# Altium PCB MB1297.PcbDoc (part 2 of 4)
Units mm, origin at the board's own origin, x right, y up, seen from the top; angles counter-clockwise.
Board outline 90.1 x 62.11 mm, 4 copper layers (Top Layer, GND, POWER+GND, Bottom Layer), stack 0.778 mm thick; 235 components, 175 nets, 1727 pads, 1 vias.
Unrouted connection lines stored in the file: 1.
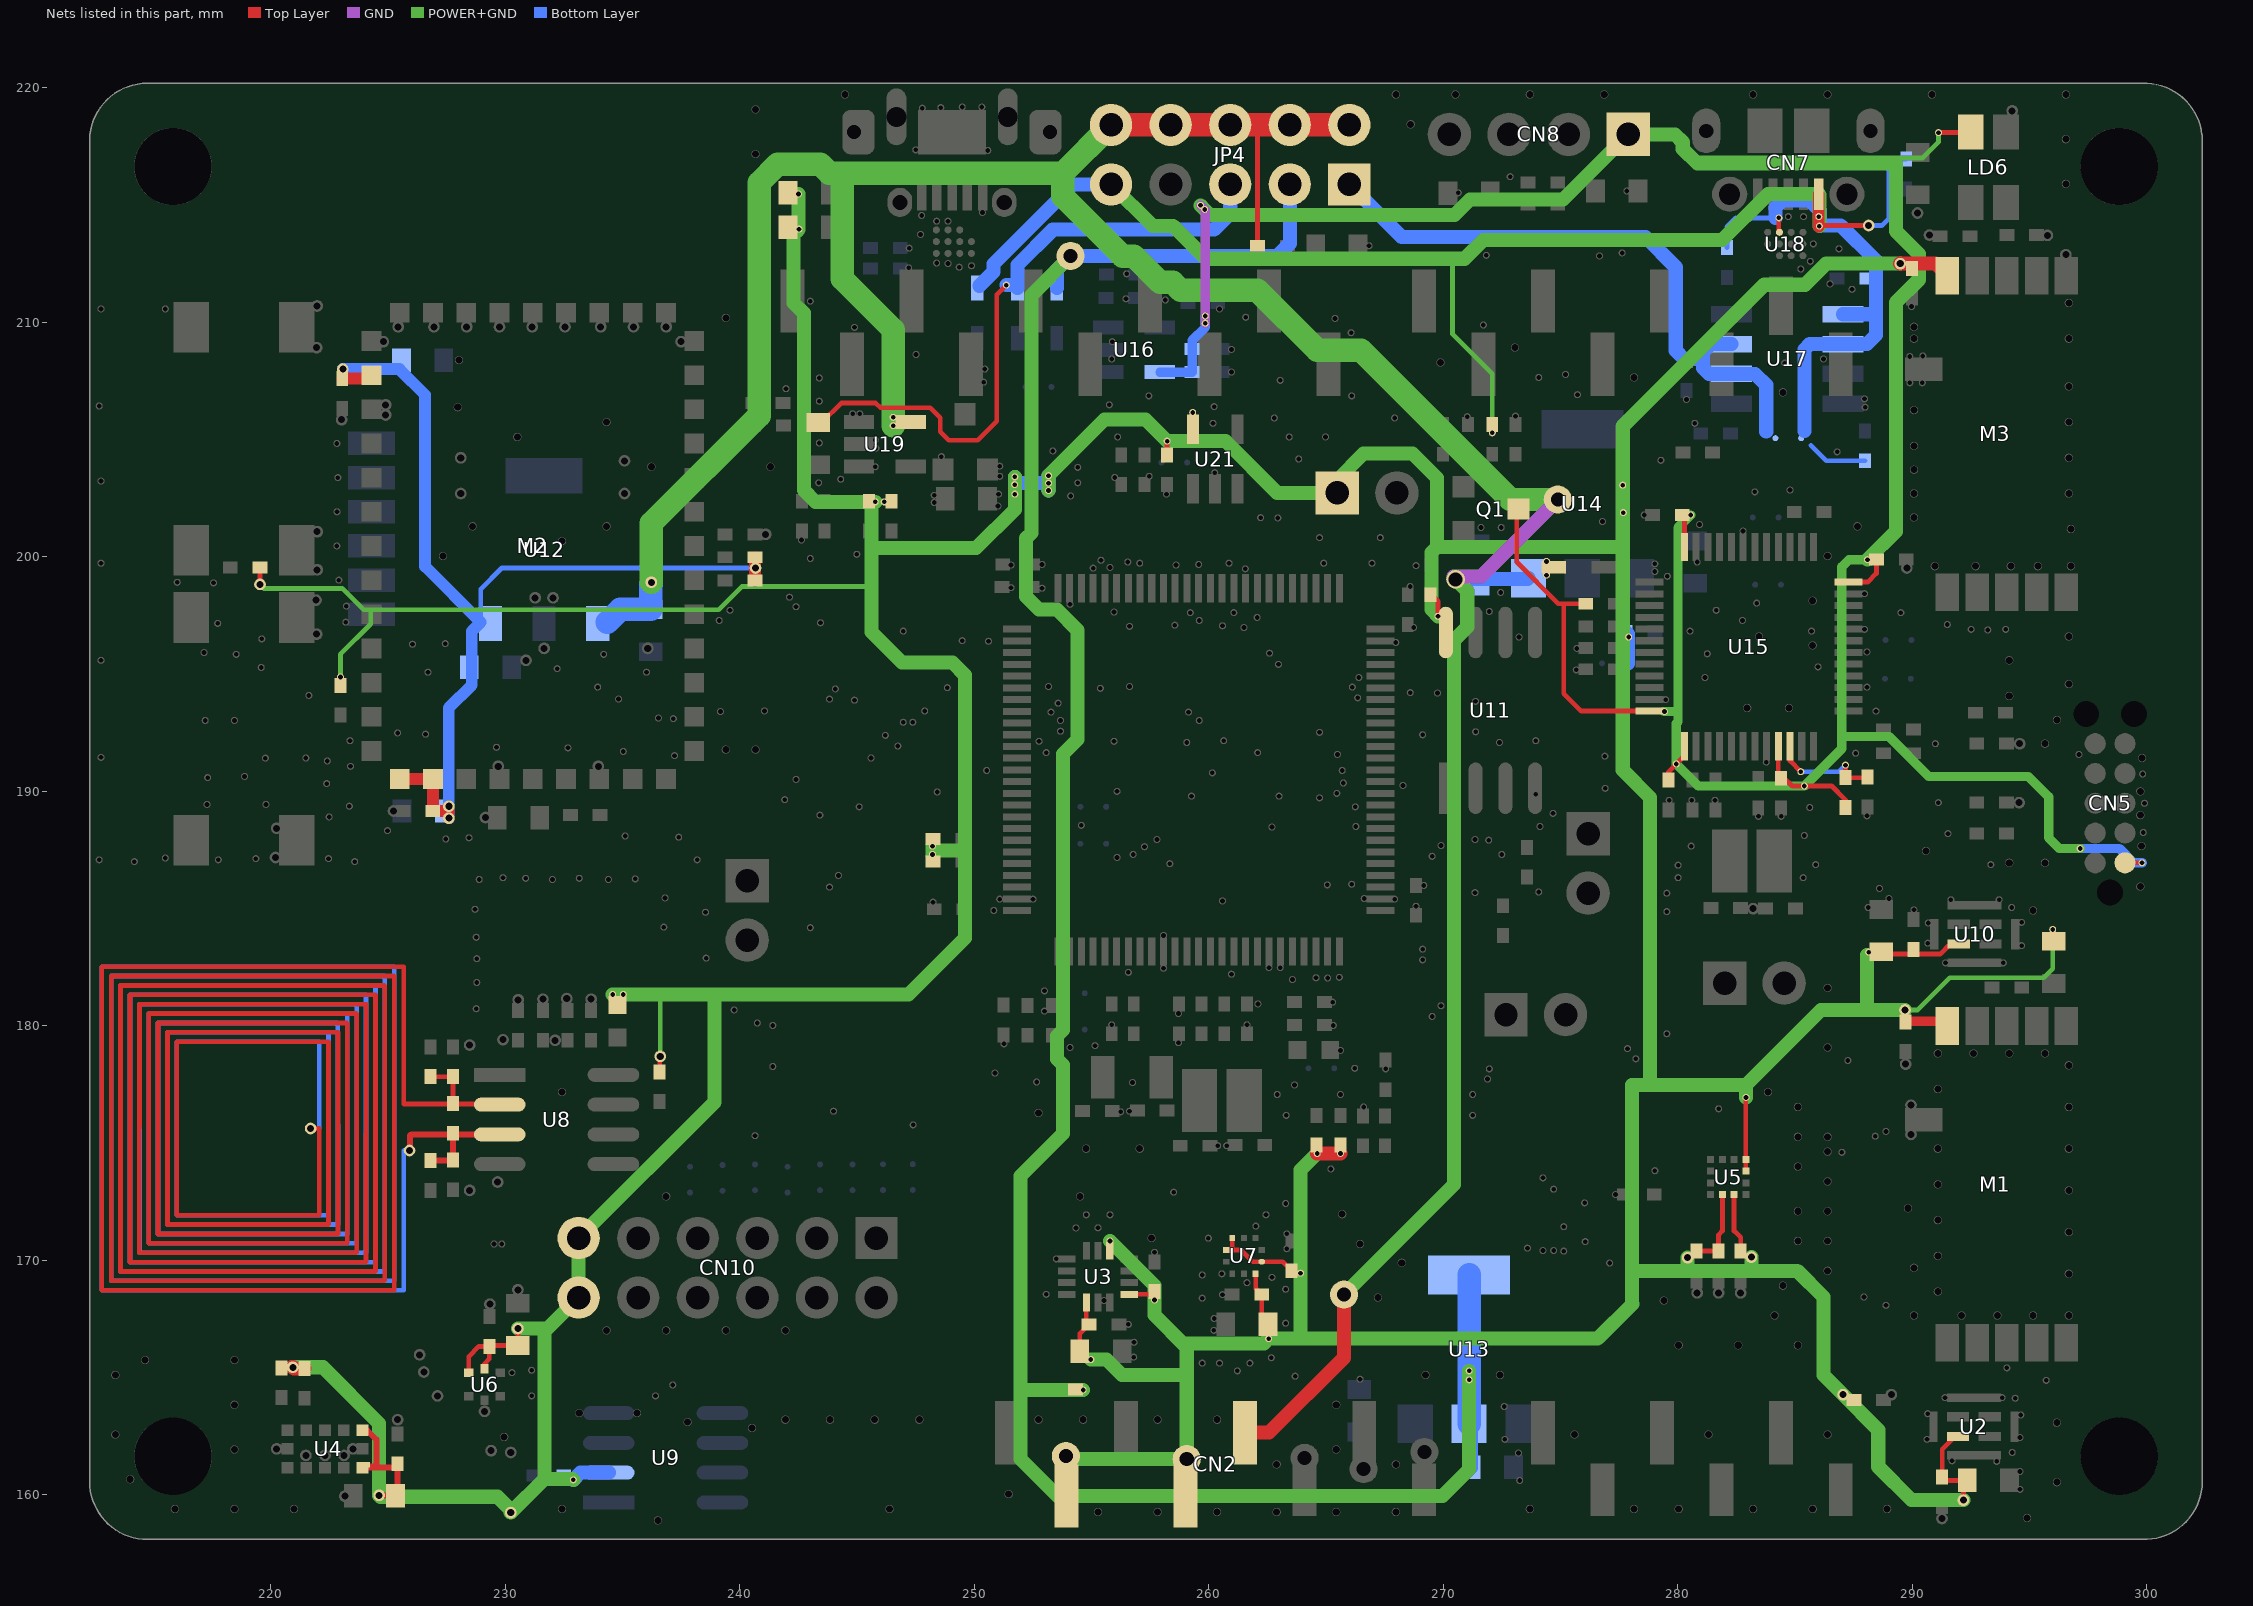
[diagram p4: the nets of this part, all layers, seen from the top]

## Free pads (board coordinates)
  round 0.3 hole 0.2 mask+0.05: 0(212.75,210.566) 0(232.893,160.63) 0(240.643,175.307) 0(247.747,214.554) 0(299.822,190.729) 1(215.494,210.566) 1(222.811,204.828) 1(247.384,175.768) 1(248.387,214.308) 1(299.847,188.239) 2(212.674,187.071) 2(222.853,203.371) 2(237.134,164.677) 2(243.992,176.352) 2(248.387,212.522) 2(299.796,186.944) 3(215.494,187.147) 3(222.818,201.914) 3(236.398,164.211) 3(279.933,191.16) 4(214.173,186.995) 4(222.809,200.457) 4(249.352,212.344) 4(285.394,190.221) 5(212.75,191.44) 5(222.894,199) 5(249.873,212.407) 5(279.476,193.904) 6(212.75,195.58) 6(223.215,197.891) 6(248.869,214.308) 6(287.96,198.425) 7(212.75,199.72) 7(223.19,197.206) 7(248.873,212.5) 7(287.96,196.901) 8(212.75,203.225) 8(247.701,213.741) 8(262.585,195.885) 8(283.769,191.237) 9(212.674,206.426) 9(255.397,199.847) 9(262.966,195.406) 9(288.087,199.873) 10(217.551,198.882) 10(255.778,199.542) 10(280.822,199.771) 11(216.002,198.907) 11(263.271,172.415) 11(278.562,201.778) 11(284.709,214.503) 12(217.729,197.155) 12(262.433,171.933) 12(280.543,201.778) 12(285.359,214.503) 13(217.297,190.576) 13(255.778,171.933) 13(282.778,201.092) 13(285.241,212.268) 14(218.872,190.627) 14(254.77,171.933) 14(284.782,202.842) 14(285.648,212.598) 15(217.195,193.015) 15(231.115,164.211) 15(275.692,196.088) 15(285.776,213.34) 16(218.44,193.015) 16(231.115,165.303) 16(275.666,195.174) 16(284.306,214.448) 17(217.145,195.91) 17(255.27,171.378) 17(286.009,214.503) 18(218.516,195.834) 18(254.33,171.374) 18(283.282,202.764) 18(286.034,214.097) 19(222.377,190.322) 19(251.358,211.582) 19(262.914,177.063) 19(289.966,210.668) 20(223.342,189.357) 20(245.11,206.096) 20(263.296,176.174) 20(286.791,204.47) 21(217.754,187.071) 21(248.285,202.616) 21(264.617,174.549) 21(292.506,196.901) 22(219.354,187.122) 22(248.285,202.311) 22(265.608,174.549) 22(293.218,196.875) 23(217.272,189.433) 23(253.06,168.541) 23(263.041,207.52) 23(293.98,196.901) 24(219.786,189.433) 24(262.056,197.409) 24(263.423,205.105) 25(222.479,188.9) 25(259.588,197.282) 25(263.83,204.165) 25(288.417,175.285) 26(222.453,187.122) 26(259.207,197.612) 27(223.571,186.995) 27(247.51,208.623) 27(253.263,193.37) 27(288.874,175.489) 28(228.879,186.233) 28(247.193,212.319) 28(253.67,193.015) 28(276.901,190.121) 29(228.752,180.721) 29(247.218,213.157) 29(259.588,193.015) 29(280.01,186.842) 30(228.778,181.839) 30(259.131,193.37) 30(263.563,181.966) 31(228.778,182.855) 31(262.077,191.643) 31(262.687,188.468) 31(293.345,186.868) 32(228.752,183.769) 32(253.06,191.643) 32(256.769,187.3) 32(285.877,186.868) 33(228.702,184.963) 33(234.569,181.331) 33(249.479,196.418) 33(274.117,188.493) 34(229.895,186.309) 34(235.026,181.331) 34(279.527,185.649) 35(230.861,186.284) 35(253.67,192.557) 35(261.214,165.278) 35(285.623,189.306) 36(232.004,186.233) 36(260.579,197.053) 36(262.09,180.924) 36(280.01,186.309) 37(233.147,186.284) 37(260.553,169.418) 37(260.629,192.151) 37(285.344,186.309) 38(234.391,186.233) 38(253.344,204.509) 38(261.62,169.037) 38(285.394,188.112) 39(235.534,186.258) 39(259.977,170.934) 39(280.568,187.655) 40(236.753,184.201) 40(261.493,196.977) 40(274.676,189.052) 41(236.804,185.445) 41(262.001,171.45) 41(279.425,193.396) 42(224.968,188.316) 42(263.906,169.443) 42(279.527,179.654) 43(227.457,187.96) 43(260.579,168.529) 43(263.652,177.47) 43(276.885,191.491) 43(277.851,179.019) 44(228.448,188.011) 44(260.223,167.513) 44(266.217,178.181) 44(278.206,178.587) 45(235.102,188.087) 45(260.21,167.005) 45(266.598,176.53) 45(281.635,197.714) 45(299.898,189.484) 46(237.388,188.036) 46(262.547,166.649) 46(267.538,178.156) 46(279.527,184.861) 46(297.104,191.567) 47(238.176,187.071) 47(252.984,181.483) 47(254.635,164.465) 47(271.348,185.674) 48(238.531,184.836) 48(254.965,165.76) 48(256.565,182.27) 49(238.557,182.88) 49(274.066,185.699) 50(239.751,180.67) 50(254.076,179.07) 50(256.807,166.497) 50(264.719,200.812) 50(283.362,198.018) 51(229.616,191.872) 51(255.143,179.146) 51(256.794,165.862) 51(264.897,199.72) 52(232.664,191.846) 52(256.565,167.259) 52(258.699,180.518) 52(271.932,187.909) 53(235.026,191.694) 53(256.083,187.173) 53(257.683,168.3) 53(272.491,187.3) 53(277.647,203.048) 54(237.211,191.516) 54(254.559,188.544) 54(257.683,170.332) 54(271.348,187.935) 54(277.673,201.879) 55(236.525,193.116) 55(255.524,168.275) 55(256.083,189.992) 55(272.44,198.476) 56(230.276,165.202) 56(237.16,193.091) 56(255.778,170.815) 57(229.845,170.688) 57(239.166,193.396) 57(243.002,184.175) 57(253.492,170.053) 57(271.704,209.88) 58(229.514,170.688) 58(240.741,180.111) 58(241.046,193.421) 58(266.09,206.858) 58(269.748,194.183) 59(236.017,195.072) 59(241.402,180.01) 59(266.827,213.258) 59(269.113,192.405) 59(289.89,208.534) 60(232.207,195.224) 60(241.402,178.257) 60(268.586,194.202) 60(290.449,208.559) 61(234.188,195.834) 61(266.624,185.42) 61(272.39,192.075) 61(289.89,207.416) 62(226.695,195.072) 62(267.919,185.395) 62(271.374,192.532) 62(290.424,207.416) 63(227.432,196.291) 63(258.14,210.947) 63(268.834,185.09) 63(271.372,193.829) 63(280.365,206.705) 64(226.035,196.266) 64(256.489,212.065) 64(269.164,185.979) 64(273.939,192.151) 64(280.721,205.689) 65(219.761,191.409) 65(256.464,210.998) 65(260.147,190.779) 65(273.939,189.865) 65(287.96,206.731) 66(221.488,191.414) 66(260.96,208.839) 66(263.042,182.474) 66(271.958,197.663) 66(287.985,206.375) 67(221.615,194.081) 67(260.96,207.874) 67(269.773,197.46) 67(284.556,208.255) 68(219.583,195.275) 68(268.732,196.977) 68(275.209,207.772) 69(219.608,196.494) 69(262.56,182.474) 69(267.97,196.342) 69(271.831,212.852) 69(286.207,208.432) 70(222.402,191.287) 70(264.566,182.042) 70(272.618,162.357) 70(276.657,212.827) 70(288.061,195.936) 71(223.393,191.059) 71(265.063,182.03) 71(272.593,163.754) 71(279.552,199.164) 71(288.061,194.437) 72(223.368,192.151) 72(265.563,182.062) 72(273.202,161.773) 72(291.118,218.084) 72(291.516,188.189) 73(225.4,192.481) 73(257.251,187.63) 73(273.253,160.604) 73(297.155,187.554) 74(226.593,192.43) 74(272.466,201.244) 74(286.868,213.131) 74(291.109,189.509) 75(255.372,194.386) 75(265.379,210.16) 75(271.602,201.244) 75(275.133,171.425) 75(290.982,192.024) 76(253.162,194.462) 76(253.162,202.819) 76(266.954,199.72) 76(275.133,170.383) 76(288.112,185.039) 77(253.162,203.454) 77(272.847,216.205) 77(274.245,170.409) 77(289.001,185.42) 78(253.162,203.136) 78(274.701,170.409) 78(290.068,184.937) 79(251.723,203.403) 79(276.047,170.79) 79(288.138,183.134) 80(251.714,203.073) 80(276.022,172.441) 80(290.678,184.379) 81(251.723,202.667) 81(266.065,209.55) 81(274.245,173.506) 81(290.659,183.515) 82(247.777,219.126) 82(274.701,173.025) 82(291.643,185.369) 83(222.961,194.869) 83(248.564,219.151) 83(257.785,187.936) 83(293.7,185.369) 84(250.317,219.177) 84(258.33,186.906) 84(294.659,184.404) 85(250.571,217.322) 85(265.049,186.004) 85(277.622,212.954) 85(294.659,183.413) 86(247.498,217.348) 86(266.09,186.03) 86(279.274,204.11) 86(291.414,182.677) 87(249.479,219.177) 87(269.519,187.223) 87(293.878,182.677) 88(250.342,214.681) 88(269.9,187.681) 88(295.986,184.099) 89(250.444,208.001) 89(269.519,180.391) 89(291.389,164.135) 90(250.393,207.442) 90(269.9,180.848) 90(293.827,164.135) 91(269.113,183.261) 91(279.019,173.812) 91(294.625,163.398) 92(269.113,182.804) 92(281.737,176.454) 92(294.589,162.433) 93(251.257,179.222) 93(253.568,193.751) 94(252.984,180.619) 94(294.259,161.798) 95(250.596,196.393) 95(256.743,177.571) 95(290.652,163.449) 96(290.627,162.357) 97(252.652,177.597) 97(254.076,197.968) 97(291.694,161.442) 98(293.599,161.417) 99(255.063,199.513) 99(294.589,160.985) 100(294.589,160.223) 101(242.113,198.272) 101(266.446,164.922) 102(242.392,197.866) 102(287.579,191.618) 103(242.392,190.5) 103(288.449,193.414) 104(241.91,189.636) 104(287.147,191.11) 105(263.271,168.758) 105(285.242,190.83) 106(243.408,188.976) 106(263.271,167.31) 106(288.061,188.951) 107(243.434,197.18) 107(262.687,169.266) 107(283.439,188.925) 108(245.085,189.332) 108(259.715,169.367) 108(284.404,188.925) 109(248.412,189.967) 109(259.715,168.377) 109(281.584,189.611) 110(244.881,209.779) 110(259.715,165.608) 110(280.594,189.611) 111(243.002,210.896) 111(260.452,165.608) 111(279.629,189.611) 112(245.77,202.336) 112(258.064,183.845) 112(261.747,165.608) 113(246.151,202.336) 113(258.064,182.448) 113(262.661,165.837) 114(242.621,200.711) 114(263.677,165.049) 115(243.002,199.923) 115(260.96,182.194) 115(265.278,181) 116(246.532,205.943) 116(260.579,185.318) 116(265.303,180.01) 117(246.532,205.588) 117(262.992,189.789) 117(265.608,178.943) 118(245.77,204.978) 118(259.258,189.789) 119(245.796,204.622) 119(259.055,192.075) 119(261.62,180.035) 120(258.597,199.644) 120(258.699,179.273) 121(245.77,203.835) 121(255.854,180.035) 121(259.563,199.669) 122(251.079,203.429) 122(260.375,174.879) 122(262.941,201.651) 123(251.079,203.86) 123(254.406,203.81) 123(260.756,174.879) 124(251.028,202.667) 124(254.406,203.149) 124(256.235,176.327) 125(251.003,202.159) 125(255.753,206.477) 125(256.616,176.352) 126(244.805,206.096) 126(260.172,205.689) 126(270.637,215.519) 127(251.562,199.644) 127(260.223,206.4) 127(277.825,215.595) 128(242.494,215.468) 128(251.562,198.679) 128(261.569,210.21) 129(242.519,213.97) 129(243.383,207.62) 129(252.882,199.669) 130(243.383,206.629) 130(247.371,192.938) 130(252.882,198.656) 131(243.383,204.851) 131(246.202,192.38) 131(262.204,201.663) 132(243.357,203.149) 132(246.736,191.922) 132(261.553,199.482) 133(244.983,200.101) 133(245.593,191.414) 133(266.243,189.332) 134(244.881,193.878) 134(266.268,188.493) 135(250.825,184.912) 135(265.735,190.348) 136(251.079,185.395) 136(265.684,190.881) 137(252.501,185.395) 137(266.395,194.843) 138(266.116,194.437) 139(266.344,193.98) 140(248.209,187.3) 140(265.455,189.906) 141(248.209,187.655) 141(265.481,191.567) 142(248.234,185.268) 143(247.879,193.421) 143(268.58,198.73) 144(241.96,207.162) 144(248.844,194.412) 145(244.2,186.406) 145(244.297,203.302) 146(243.818,185.906) 146(248.59,204.267) 147(244.069,194.361) 148(243.818,193.925) 149(239.116,197.282) 149(277.343,172.796) 150(239.573,197.714) 150(282.905,176.936) 151(271.247,176.174) 152(246.964,192.938) 152(271.247,177.063) 153(233.934,194.437) 153(265.608,177.063) 154(234.823,193.929) 155(246.964,196.825) 155(258.547,197.079) 156(250.52,190.881) 156(258.496,172.898) 157(273.583,170.51) 159(277.089,169.875) 160(291.49,197.104) 161(288.874,168.072) 162(295.707,164.871) 163(294.03,165.405) 164(287.934,168.427) 165(294.386,164.109) 166(294.234,185.039) 167(286.995,174.6) 168(288.595,185.852) 169(287.249,178.511) 171(257.438,206.858) 172(257.454,203.429) 173(258.191,202.667) 174(259.309,206.146) 175(260.248,203.581) 177(258.216,204.927) 179(257.048,199.72) 180(256.54,199.771) 181(256.108,205.105)
  round 3.3 hole 3.3 unplated mask+0.05: 0(215.819,161.64) 0(215.819,216.64) 0(298.819,161.64) 0(298.819,216.64)
  round 0.5 hole 0.3 mask+0.05: 0(225.908,174.676) 0(229.387,161.874) 0(288.138,214.122) 1(221.691,175.614) 1(230.226,161.798) 1(290.22,214.655) 2(229.337,168.123) 2(230.53,168.732) 3(229.146,188.874) 4(227.584,189.357) 4(230.226,159.233) 5(223.152,159.931) 5(227.584,188.849) 6(224.612,159.969) 6(231.648,196.088) 7(223.491,161.95) 7(231.267,198.247) 8(223.114,161.671) 8(232.029,198.247) 9(222.301,161.671) 9(228.092,204.216) 10(221.488,161.671) 10(228.092,202.692) 11(220.243,161.95) 11(235.077,204.089) 12(225.4,163.195) 12(235.077,202.692) 13(220.929,165.43) 14(227.101,164.211) 15(229.108,163.551) 15(236.22,198.907) 16(224.79,209.169) 16(230.53,167.081) 17(225.425,209.804) 17(226.517,165.227) 18(226.339,165.964) 18(226.949,209.804) 19(228.346,209.804) 20(229.743,209.804) 21(231.14,209.804) 22(232.537,209.804) 23(234.061,209.804) 24(228.473,179.172) 24(235.458,209.804) 25(228.473,172.974) 25(236.855,209.804) 26(229.667,173.33) 26(237.49,209.169) 27(230.543,181.102) 27(240.665,199.517) 28(231.597,181.127) 28(241.097,200.952) 29(232.613,181.153) 30(233.655,181.127) 31(232.118,179.375) 32(229.895,179.4) 33(236.601,178.689) 37(292.176,159.766) 39(291.262,158.979) 44(287.045,164.262) 45(289.103,164.262) 50(294.577,192.024) 51(294.551,189.509) 54(289.687,180.67) 56(289.941,176.606) 57(289.941,175.362) 58(289.712,178.359) 68(283.134,170.129) 69(280.416,170.104) 70(280.822,168.605) 71(281.737,168.605) 72(282.677,168.605) 81(289.763,199.517) 82(283.21,184.988) 83(223.063,208.001) 84(223.012,205.842) 85(224.892,206.477) 86(224.892,206.045) 87(219.532,198.819) 88(230.873,195.58) 89(236.068,196.088) 91(225.222,189.154) 92(229.692,191.059) 93(233.959,191.059) 94(220.243,188.417) 95(220.193,187.173) 96(221.92,198.145) 97(221.945,196.698) 98(221.971,201.066) 99(221.971,199.441) 100(221.971,210.693) 101(221.945,208.915) 107(294.259,219.011) 108(296.545,212.877) 109(289.484,212.496) 110(290.728,213.716) 111(295.758,213.703)
  round 1.2 hole 0.6 mask+0.05: 48(253.897,161.645) 48(254.102,212.827) 48(259.054,161.518) 48(264.083,161.568) 48(265.76,168.529) 48(266.597,161.086) 48(269.189,161.823) 48(274.879,202.438)
  round 0.8 hole 0.6 mask+0.05: 48(270.521,199.034)
  round 0.3 hole 0.2 mask-0.01: 182(271.098,165.278) 183(271.098,164.897) 184(256.616,197.028) 186(264.719,189.713) 187(264.719,192.507) 191(255.956,197.637) 192(255.956,192.126) 193(256.616,194.462) 194(252.755,192.126) 195(271.958,178.156) 196(265.201,173.888) 197(250.875,177.978) 198(261.063,197.613) 199(271.882,177.724) 202(260.858,199.72) 203(262.788,205.918) 204(267.919,205.918) 205(274.396,199.212) 206(274.396,199.796) 207(272.085,205.283) 208(259.639,214.986) 209(259.817,214.808) 210(259.842,210.261) 211(259.842,209.956) 212(254.102,202.59) 213(264.973,205.105) 215(276.784,201.498) 216(282.753,197.282) 217(280.924,201.371) 218(279.019,199.695) 219(279.019,199.365) 221(277.901,196.571) 222(280.518,196.825) 223(275.717,206.908) 224(274.066,207.645) 225(271.018,205.969) 226(273.075,205.994) 228(273.228,196.571) 229(268.276,190.245) 230(268.834,199.619) 231(260.452,210.566) 232(255.88,209.169) 233(255.854,208.432) 234(263.322,171.12) 235(263.322,170.485) 236(255.981,203.378) 237(286.487,211.633) 238(287.426,211.404) 239(281.153,194.843) 241(285.979,195.301) 244(267.31,200.812) 245(289.509,197.612) 246(285.699,196.825) 247(281.254,195.859)
  round 0.35 hole 0.3 mask-0.01: 249(296.672,207.264) 250(296.672,209.296) 251(296.672,210.82) 252(296.672,205.74) 253(296.672,204.216) 254(296.672,202.692) 255(296.759,201.179) 256(296.759,199.593) 257(295.351,199.593) 258(294.198,199.593) 259(292.699,199.593) 260(290.957,199.593) 261(290.068,201.676) 262(290.068,202.692) 263(290.068,203.708) 264(290.068,204.724) 265(290.068,206.248) 266(290.068,209.296) 267(290.068,209.804) 268(296.672,196.596) 269(296.672,194.564) 270(294.132,195.58) 271(294.132,194.056) 272(296.164,193.04) 273(295.656,192.024) 274(295.656,186.944) 275(294.132,186.944) 276(290.576,187.452) 277(295.148,184.912) 278(299.72,185.928) 279(299.72,188.976) 280(299.72,189.992) 281(299.796,191.414) 282(299.771,187.655) 283(296.672,178.308) 284(296.672,176.53) 285(296.672,174.752) 286(296.672,172.974) 287(296.672,171.196) 288(296.672,167.64) 289(296.672,169.418) 290(291.084,178.816) 291(291.084,177.292) 292(291.084,174.752) 293(291.084,173.228) 294(291.084,171.704) 295(291.084,170.18) 296(291.084,168.656) 297(292.1,167.64) 298(293.624,167.64) 299(295.148,167.64) 300(292.608,178.816) 301(294.132,178.816) 302(295.656,178.816) 303(289.814,172.212) 304(290.068,169.672) 305(290.068,167.64) 306(286.385,169.545) 307(286.385,170.815) 308(286.385,172.085) 309(286.385,173.355) 310(286.385,174.625) 311(283.845,177.165) 312(285.115,176.53) 313(286.385,175.26) 314(285.115,175.26) 315(285.115,173.99) 316(285.115,172.085) 317(285.115,170.815) 318(284.48,168.91) 319(284.124,167.64) 320(285.115,166.37) 321(286.385,179.07) 322(286.385,181.61) 327(240.665,219.075) 328(244.475,219.71) 329(240.665,217.17) 330(296.545,219.71) 331(290.83,219.71) 332(296.545,217.805) 333(296.545,215.9) 334(267.97,219.71) 335(268.605,218.44) 336(270.51,219.71) 337(273.685,219.71) 338(276.86,219.71) 339(283.21,219.71) 340(286.385,219.71) 341(273.05,208.915) 342(269.875,208.28) 343(278.13,207.645) 344(284.48,207.01) 345(287.655,201.295) 346(286.385,200.025) 347(285.75,198.12) 348(285.75,196.215) 349(281.305,162.56) 350(283.21,159.385) 351(285.75,159.385) 352(280.035,159.385) 353(278.13,159.385) 354(273.685,159.385) 355(267.97,159.258) 356(265.43,159.258) 357(262.89,159.258) 358(260.35,159.258) 359(257.81,159.258) 360(255.27,159.258) 361(275.59,162.56) 362(265.43,161.925) 363(262.89,161.29) 364(267.97,161.29) 365(269.24,165.1) 366(272.415,165.1) 367(280.035,166.37) 368(282.575,166.37) 369(279.4,168.275) 370(286.385,162.56) 371(288.925,159.385) 372(257.81,163.195) 373(260.35,163.195) 374(254.635,163.195) 375(252.73,163.195) 376(265.43,163.83) 377(251.46,160.02) 378(247.65,163.195) 379(246.38,159.385) 380(236.499,158.902) 381(232.41,159.385) 382(229.946,162.458) 383(220.98,159.385) 384(218.44,159.385) 385(215.9,159.385) 386(213.995,160.655) 387(213.36,162.56) 388(213.36,165.1) 389(214.63,165.735) 390(218.44,165.735) 391(218.44,163.83) 392(218.44,161.925) 393(233.147,163.474) 394(235.61,163.474) 395(237.769,163.093) 396(240.513,162.839) 397(241.935,163.195) 398(243.84,163.195) 399(245.745,163.195) 400(234.315,167.005) 401(236.855,167.005) 402(239.395,167.005) 403(241.935,167.005) 404(232.41,177.165) 405(236.855,172.72) 406(227.965,206.375) 407(230.505,205.105) 408(234.315,205.74) 409(241.3,203.835) 410(236.22,203.835) 411(227.33,200.025) 412(228.6,201.295) 413(232.41,200.66) 414(234.315,201.295) 415(240.665,191.77) 416(239.395,191.77) 417(228.016,208.382) 418(239.395,210.185) 420(252.73,176.276) 421(257.556,170.942) 422(257.048,174.752) 423(254.762,174.752) 424(254.508,172.72) 425(265.684,171.958) 426(266.446,170.688) 427(268.224,169.885) 428(267.208,168.402) 429(296.164,163.068) 430(296.164,160.528) 431(294.894,159.004) 432(282.956,193.548) 433(284.734,193.548) 434(283.464,196.596)

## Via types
v1: diameter 0.4, hole 0.2, Top Layer to Bottom Layer, tented both sides, 1 vias

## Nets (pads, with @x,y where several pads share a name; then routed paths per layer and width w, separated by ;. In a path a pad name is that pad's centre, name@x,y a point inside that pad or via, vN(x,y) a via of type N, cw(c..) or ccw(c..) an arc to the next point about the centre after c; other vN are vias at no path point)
3V3: C16.1 C17.2 C18.1 C19.1 C20.1 C21.1 C22.1 C24.1 C25.1 C26.1 C27.1 C28.1 C29.1 C30.1 C31.1 C33.1 C42.1 C43.1 C45.1 C46.1 C48.1 C73.1 C74.1 CN2.2 CN2.4 CN10.6 CN10.12 JP5.1 L2.2 LD4.A LD8.A LD9.A M1.5 M3.5 pad.0@232.893,160.63 pad.4@230.226,159.233 pad.6@224.612,159.969 pad.13@220.929,165.43 pad.16@230.53,167.081 pad.21@264.617,174.549 pad.22@265.608,174.549 pad.33@234.569,181.331 pad.33@236.601,178.689 pad.34@235.026,181.331 pad.37@292.176,159.766 pad.42@263.906,169.443 pad.44@287.045,164.262 pad.46@262.547,166.649 pad.48@253.897,161.645 pad.48@254.965,165.76 pad.48@259.054,161.518 pad.53@257.683,168.3 pad.53@277.647,203.048 pad.54@277.673,201.879 pad.54@289.687,180.67 pad.56@255.778,170.815 pad.67@269.773,197.46 pad.68@283.134,170.129 pad.69@280.416,170.104 pad.76@253.162,202.819 pad.77@253.162,203.454 pad.78@253.162,203.136 pad.79@251.723,203.403 pad.79@288.138,183.134 pad.80@251.714,203.073 pad.81@251.723,202.667 pad.83@222.961,194.869 pad.87@219.532,198.819 pad.88@295.986,184.099 pad.109@289.484,212.496 pad.112@245.77,202.336 pad.113@246.151,202.336 pad.128@242.494,215.468 pad.129@242.519,213.97 pad.140@248.209,187.3 pad.141@248.209,187.655 pad.150@282.905,176.936 pad.174 pad.177 pad.221 R4.1 R8.1 R9.1 R10.1 R11.1 R14.1 R15.1 R23.2 R26.2 R58.1 R62.1 R67.1 SB4.2 U2.1 U3.5 U3.8 U3.12 U4.1 U4.11 U5.5 U5.6 U5.9 U5.10 U6.1 U6.6 U7.1 U7.5 U7.6 U7.10 U9.2 U10.1 U11.8 U21.5 | length 377.1
  Top Layer w0.204: pad.87@219.532,198.819 R23.2@219.532,199.542 ; U6.1@228.433,165.194 228.433,165.886 228.867,166.319 C28.1@229.311,166.319 ; U6.6@229.108,165.369 229.108,165.583 229.311,165.786 C28.1@229.311,166.319 ; pad.16@230.53,167.081 C27.1@230.53,166.357 229.349,166.357 C28.1@229.311,166.319 ; R4.1@236.576,178.029 pad.33@236.576,178.664 ; C18.1@254.495,166.116 254.495,166.865 C19.1@254.889,167.259 254.77,167.378 U3.5@254.77,168.191 ; U3.8@256.6,168.541 257.568,168.541 C20.1@257.683,168.656 ; C73.1@258.216,204.343 pad.177@258.216,204.927 ; U7.6@260.73,170.43 260.981,170.43 ; U7.5@260.993,170.943 260.993,170.442 261.001,170.434 261.366,170.434 261.87,169.93 U7.1@262.256,169.93 263.14,169.93 C31.1@263.525,169.545 ; U7.10@261.993,169.417 261.993,168.791 C29.1@262.255,168.529 262.255,167.526 C30.1@262.522,167.259 ; C48.1@269.469,198.399 269.773,198.095 pad.67@269.773,197.46 ; U11.8@270.104,195.871 270.104,197.409 U11.8@270.154,197.46 ; C24.1@280.797,170.383 C25.1@281.737,170.383 281.737,171.086 281.897,171.247 U5.5@281.897,172.795 ; U5.6@282.397,172.795 282.397,171.247 282.677,170.967 C26.1@282.677,170.383 ; U5.9@282.897,173.795 U5.10@282.897,174.295 282.897,176.928 pad.150@282.905,176.936 ; C46.1@288.671,183.147 288.765,183.052 291.193,183.052 291.622,183.481 U10.1@291.984,183.481 ; C43.1@289.712,180.162 C43.1@289.738,180.188 ; M1.5@291.186,180.188 291.389,179.984 M1.5@291.49,179.984 ; U2.1@291.95,162.477 291.812,162.477 291.271,161.937 291.271,160.766 C17.2@291.262,160.757 291.414,160.604 292.189,160.604 292.176,160.592 pad.37@292.176,159.766
  Top Layer w0.254: U4.11@223.901,162.75 224.092,162.75 224.501,162.341 224.501,161.198 223.949,161.198 U4.1@223.901,161.15 225.235,161.15 C22.1@225.4,161.315 225.4,160.033 C21.1@225.311,159.944 ; pad.6@224.612,159.969 C21.1@225.285,159.969
  Top Layer w0.4: C43.1@289.738,180.188 M1.5@291.186,180.188
  Top Layer w0.6: pad.13@220.929,165.43 220.98,165.379 R14.1@221.437,165.379 ; pad.21@264.617,174.549 pad.22@265.608,174.549 ; pad.109@289.484,212.496 290.982,212.496 M3.5@291.49,211.988
  POWER+GND w0.204: pad.87@219.532,198.819 219.705,198.646 223.041,198.646 223.948,197.739 224.257,197.739 ; pad.83@222.961,194.869 222.961,195.834 224.257,197.129 224.257,197.739 ; 236.576,181.305 236.601,181.28 pad.33@236.601,178.689 ; 245.61,198.755 245.585,198.73 240.088,198.73 239.098,197.739 224.257,197.739 ; 245.72,200.363 pad.112@245.72,202.286 ; 259.232,204.927 259.309,205.003 pad.174@259.309,206.146 ; pad.54@289.687,180.67 290.22,180.67 291.592,182.042 295.605,182.042 295.986,182.423 pad.88@295.986,184.099
  POWER+GND w0.6: pad.13@220.929,165.43 222.221,165.43 224.612,163.039 pad.6@224.612,159.969 224.671,159.91 229.663,159.91 230.226,159.347 pad.4@230.226,159.233 231.667,160.674 ; pad.16@230.53,167.081 231.8,167.081 ; pad.0@232.893,160.63 232.849,160.674 231.667,160.674 ; pad.33@234.569,181.331 pad.34@235.026,181.331 238.912,181.331 ; pad.128@242.494,215.468 242.494,213.944 242.291,213.741 242.291,210.827 242.722,210.395 242.722,202.844 243.23,202.336 pad.112@245.77,202.336 245.72,202.286 245.61,202.176 245.61,198.755 245.61,196.782 246.913,195.478 249.072,195.478 249.606,194.945 249.606,187.477 ; 245.72,200.363 250.071,200.363 251.723,202.015 pad.81@251.723,202.667 pad.79@251.723,203.403 ; pad.140@248.209,187.3 pad.141@248.209,187.655 248.387,187.477 249.606,187.477 ; pad.76@253.162,202.819 pad.78@253.162,203.136 pad.77@253.162,203.454 255.549,205.842 257.302,205.842 pad.177@258.216,204.927 259.232,204.927 260.706,204.927 262.915,202.717 JP5.1@265.477,202.717 265.477,203.272 266.598,204.394 268.681,204.394 269.723,203.352 269.723,200.41 ; pad.48@253.897,161.645 254.024,161.518 pad.48@259.054,161.518 259.054,165.1 ; pad.48@254.965,165.76 255.626,165.76 256.286,165.1 259.054,165.1 ; pad.56@255.778,170.815 257.683,168.91 pad.53@257.683,168.3 257.683,167.652 259.054,166.281 ; 264.033,166.649 276.581,166.649 278.066,168.135 ; pad.21@264.617,174.549 263.906,173.838 pad.42@263.906,169.443 263.906,166.649 pad.46@262.547,166.649 262.351,166.453 259.054,166.453 259.054,165.1 ; pad.67@269.773,197.46 269.494,197.739 269.494,200.182 269.723,200.41 ; 278.046,168.156 278.046,177.462 278.816,177.462 ; 278.097,169.545 283.134,169.545 ; 280.416,169.596 pad.69@280.416,170.104 ; pad.150@282.905,176.936 282.897,177.462 ; pad.68@283.134,170.129 283.134,169.545 ; pad.79@288.061,183.007 288.061,180.67 ; pad.109@289.484,212.496 286.327,212.496 285.428,211.597 283.683,211.597 277.647,205.562 pad.53@277.647,203.048 277.647,200.41 ; pad.54@289.687,180.67 288.061,180.67 ; pad.37@292.176,159.766 289.966,159.766 288.544,161.188 288.544,162.763 pad.44@287.045,164.262 286.207,165.1 286.207,168.427 285.09,169.545 283.134,169.545 ; 231.667,160.674 231.667,166.947 231.8,167.081 ; 231.8,167.081 CN10.12@233.121,168.402 CN10.6@233.121,170.942 238.912,176.733 238.912,181.331 ; 238.912,181.331 247.193,181.331 249.606,183.744 249.606,187.477 ; 269.723,200.41 277.647,200.41 ; 277.647,200.41 277.647,190.906 278.816,189.738 278.816,177.462 ; 278.816,177.462 282.897,177.462 ; 282.897,177.462 286.106,180.67 288.061,180.67
  Bottom Layer w0.6: pad.0@232.893,160.63 233.197,160.934 U9.2@234.405,160.934 ; pad.81@251.723,202.667 pad.79@251.723,203.403 ; pad.80@251.787,203.136 pad.78@253.162,203.136 ; pad.76@253.162,202.819 pad.78@253.162,203.136 ; pad.77@253.162,203.454 pad.78@253.162,203.136 ; C42.1@277.749,196.825 277.866,196.707 SB4.2@277.866,195.453
3V3_ST_LINK: C55.1 C59.1 C60.1 C61.1 C62.1 C63.1 CN5.1 CN8.1 LD6.4 pad.2@299.796,186.944 pad.3@279.933,191.16 pad.4@285.394,190.221 pad.9@288.087,199.873 pad.12@280.543,201.778 pad.41@279.425,193.396 pad.72@291.118,218.084 pad.73@297.155,187.554 pad.208 pad.209 pad.210 pad.211 Q1.3 R30.1 R40.2 U15.1 U15.9 U15.24 U15.36 U15.48 U16.5 | length 140.3
  Top Layer w0.204: Q1.3@273.202,202.032 273.124,201.954 273.124,199.773 274.904,197.993 275.133,197.993 ; R30.1@276.073,197.993 275.133,197.993 ; U15.48@278.782,193.414 275.876,193.414 275.133,194.158 275.133,197.993 ; C60.1@279.603,190.475 279.603,190.83 280.282,191.509 U15.1@280.282,191.914 ; U15.36@280.282,200.414 C63.1@280.282,201.683 ; U15.9@284.282,191.914 284.282,190.66 C61.1@284.391,190.551 284.543,190.551 284.874,190.221 pad.4@285.394,190.221 286.563,190.221 287.147,189.636 R40.2@287.147,189.306 ; U15.24@287.282,198.914 288.094,198.914 288.468,199.288 C62.1@288.468,199.873 ; pad.72@291.118,218.084 LD6.4@292.52,218.084 ; CN5.1@299.068,186.944 pad.2@299.796,186.944
  GND w0.4: pad.208@259.639,214.986 pad.209@259.817,214.808 259.842,214.782 pad.210@259.842,210.261 pad.211@259.842,209.956
  POWER+GND w0.204: 280.876,217.004 290.436,217.004 291.118,217.686 pad.72@291.118,218.084
  POWER+GND w0.4: pad.41@279.425,193.396 280.004,193.396 ; 279.933,192.888 pad.3@279.933,191.16 280.873,190.221 pad.4@285.394,190.221 286.995,191.821 286.995,192.329 ; 280.004,192.959 280.004,193.396 ; pad.12@280.543,201.778 280.004,201.239 280.004,193.396 ; pad.9@288.087,199.873 287.299,199.873 286.995,199.568 286.995,192.329 ; pad.73@297.155,187.554 296.266,187.554 295.808,188.011 295.808,189.763 294.945,190.627 290.703,190.627 289.001,192.329 286.995,192.329
  POWER+GND w0.6: pad.208@259.639,214.986 pad.209@259.817,214.808 260.052,214.573 270.471,214.573 271.138,215.24 275.107,215.24 CN8.1@277.876,218.008 279.872,218.008 280.207,217.673 280.207,217.393 280.836,216.764 289.293,216.764 289.293,213.881 290.271,212.903 290.271,211.811 289.293,210.833 289.293,201.079 pad.9@288.087,199.873
  Bottom Layer w0.4: U16.5@257.912,207.867 259.277,207.867 C55.1@259.283,207.874 C59.1@259.283,208.864 259.283,209.22 259.842,209.779 pad.211@259.842,209.956 pad.210@259.842,210.261 ; pad.73@297.155,187.554 298.831,187.554 299.441,186.944 pad.2@299.796,186.944
3V3_WIFI: C44.1 C47.1 C50.1 C75.1 C76.1 M2.2 M2.14 M2.15 pad.4@227.584,189.357 pad.5@227.584,188.849 pad.27@240.665,199.517 pad.83@223.063,208.001 R65.2 R66.2 U12.3 | length 43.3
  Top Layer w0.5: C44.1@223.037,207.594 224.138,207.594 M2.2@224.285,207.742 ; M2.14@225.485,190.515 M2.15@226.905,190.515 C47.1@226.905,189.154 ; C47.1@226.898,189.154 C47.1@226.905,189.154 ; pad.4@227.533,189.154 C47.1@226.905,189.154 ; pad.5@227.584,188.849 pad.4@227.584,189.357 ; R66.2@240.64,198.984 R65.2@240.64,199.974
  Bottom Layer w0.204: U12.3@228.948,197.204 228.948,198.62 229.845,199.517 pad.27@240.665,199.517
  Bottom Layer w0.5: pad.83@223.063,208.001 225.476,208.001 226.568,206.908 226.568,199.584 228.948,197.204 228.562,196.818 228.562,195.504 228.562,194.526 227.584,193.548 pad.4@227.584,189.357 pad.5@227.584,188.849
5V: C40.1 C49.1 CN2.5 D2.1 JP4.2 JP4.4 JP4.6 JP4.8 JP4.10 pad.15@236.22,198.907 pad.48@265.76,168.529 pad.48@270.521,199.034 pad.48@274.879,202.438 pad.116@246.532,205.943 pad.117@246.532,205.588 pad.205 pad.206 R25.1 U12.1 U14.3 U19.5 | length 143.2
  Top Layer w0.204: R25.1@262.077,213.258 262.077,218.364 262.128,218.415
  Top Layer w0.6: CN2.5@261.545,162.642 262.566,162.642 265.76,165.837 pad.48@265.76,168.529
  Top Layer w1: JP4.10@255.829,218.415 JP4.8@258.369,218.415 JP4.6@260.909,218.415 262.128,218.415 JP4.4@263.449,218.415 JP4.2@265.989,218.415
  GND w0.6: pad.48@270.521,199.034 270.429,199.161 271.602,199.161 pad.48@274.879,202.438
  POWER+GND w0.6: pad.48@265.76,168.529 270.452,173.221 270.452,196.437 271.018,197.002 271.018,198.537 pad.48@270.476,199.079
  POWER+GND w1: pad.15@236.22,198.907 236.22,201.422 240.817,206.019 240.817,215.951 241.605,216.738 243.434,216.738 243.814,216.358 244.361,216.358 ; pad.117@246.532,205.588 pad.116@246.532,205.943 246.532,209.677 244.361,211.849 244.361,216.358 ; JP4.10@255.829,218.415 253.772,216.358 ; pad.48@274.879,202.438 272.847,202.438 266.487,208.798 264.627,208.798 262.072,211.353 258.797,211.353 258.452,211.699 257.918,211.699 256.801,212.817 256.321,212.817 253.772,215.366 253.772,216.358 ; 244.361,216.358 253.772,216.358
  Bottom Layer w0.6: pad.48@270.521,199.034 272.202,199.057 272.212,199.047 273.586,199.047 U14.3@273.624,199.085
  Bottom Layer w1: U12.1@234.348,197.204 234.895,197.752 C49.1@236.195,197.752 236.195,198.788 pad.15@236.22,198.813
5V_ARD: C39.1 D3.1 JP4.3 pad.47@254.635,164.465 pad.48@254.102,212.827 pad.182 pad.183 R3.1 U13.2 U13.4 | length 103.6
  POWER+GND w0.6: pad.48@254.102,212.827 252.425,211.15 252.425,201.016 252.197,200.787 252.197,198.298 252.755,197.739 253.524,197.739 254.4,196.864 254.4,192.202 253.778,191.58 253.778,179.807 253.524,179.553 253.524,178.581 253.778,178.327 253.778,175.394 251.968,173.584 251.968,164.389 ; pad.47@254.635,164.465 252.044,164.465 251.968,164.389 ; pad.182@271.098,165.278 271.098,161.078 269.964,159.944 253.543,159.944 251.968,161.519 251.968,164.389
  Bottom Layer w0.6: D3.1@253.517,211.458 253.517,212.242 pad.48@254.102,212.827 262.915,212.827 263.449,213.36 JP4.3@263.449,215.875 ; C39.1@271.183,161.163 U13.2@271.183,162.933
  Bottom Layer w1: U13.2@271.098,163.017 U13.4@271.098,169.367
5V_ST_LINK: C65.1 JP4.1 SB11.1 U17.6 U17.7 | length 27.3
  Bottom Layer w0.6: JP4.1@265.989,215.875 268.224,213.639 278.613,213.639 279.908,212.344 279.908,208.788 280.264,208.432 281.076,208.432 ; U17.7@282.283,209.067 281.407,209.067 281.076,208.737 281.076,208.432 ; 283.769,205.334 283.769,207.315 283.286,207.797 U17.6@282.283,207.797 281.33,207.797 281.076,208.051 281.076,208.432
5V_USB_CHARGER: C64.1 CN7.1 D4.1 JP4.9 pad.0@288.138,214.122 pad.16@284.306,214.448 pad.17@286.009,214.503 pad.18@286.034,214.097 pad.207 R48.1 R49.2 R51.2 R52.2 SB11.2 U17.1 U17.2 U18.B3 | length 81.2
  Top Layer w0.204: U18.B3@284.306,213.835 pad.16@284.306,214.448 ; pad.18@286.009,214.071 pad.18@286.034,214.097 286.059,214.122 pad.0@288.138,214.122
  Top Layer w0.5: pad.18@286.009,214.071 pad.17@286.009,214.503 CN7.1@286.009,215.458
  POWER+GND w0.204: 270.383,212.706 270.383,209.499 272.085,207.797 pad.207@272.085,205.283
  POWER+GND w0.6: JP4.9@255.829,215.875 257.607,214.097 258.477,214.097 259.867,212.706 270.383,212.706 270.905,212.706 271.704,213.506 281.885,213.506 283.838,215.458 286.009,215.458 286.034,215.433 pad.18@286.034,214.097
  Bottom Layer w0.204: R49.2@282.092,213.182 282.092,214.073 282.468,214.448 pad.16@284.157,214.448 ; 285.674,204.749 286.334,204.089 R51.2@287.985,204.089 ; pad.0@288.138,214.122 288.696,214.122 289.009,214.434 289.009,216.669 289.293,216.954 R52.2@289.738,216.954
  Bottom Layer w0.6: D4.1@250.218,211.554 250.815,212.151 250.815,212.486 254.203,215.875 JP4.9@255.829,215.875 ; pad.16@284.157,214.448 284.157,214.891 284.455,215.189 285.623,215.189 286.059,214.752 286.059,214.122 286.944,214.122 288.442,212.623 288.442,209.448 288.061,209.067 U17.2@287.033,209.067 285.623,209.067 285.394,208.839 285.394,205.359 ; U17.1@287.033,210.337 288.341,210.337
5V_USB_FS: D5.1 JP4.5 pad.19@251.358,211.582 R61.1 | length 28
  Top Layer w0.204: R61.1@243.332,205.727 243.497,205.727 244.323,206.553 245.796,206.553 245.999,206.35 248.107,206.35 248.539,205.918 248.539,205.334 248.907,204.966 250.139,204.966 250.952,205.779 250.952,211.176 pad.19@251.358,211.582
  Bottom Layer w0.6: pad.19@251.358,211.582 251.71,211.582 D5.1@251.835,211.457 251.835,212.44 253.34,213.944 260.223,213.944 260.909,214.63 JP4.5@260.909,215.875
AIN_1: pad.104@287.147,191.11 pad.105@285.242,190.83 R40.1 R41.1 U15.10 | length 4.8
  Top Layer w0.204: U15.10@284.782,191.914 284.782,191.29 pad.105@285.242,190.83 ; pad.104@287.147,191.11 R40.1@287.147,190.576 288.061,190.576 R41.1@288.087,190.602
  Bottom Layer w0.204: pad.105@285.242,190.83 286.868,190.83 pad.104@287.147,191.11
ANT: C53.1 C69.1 C70.1 C70.2 C71.1 C72.1 pad.0@225.908,174.676 pad.1@221.691,175.614 U8.2 U8.3 | length 734.4
  Top Layer w0.2: pad.1@221.691,175.615 222.056,175.615 222.054,171.916 215.984,171.916 215.984,179.316 222.456,179.316 222.454,171.516 215.584,171.516 215.584,179.716 222.856,179.716 222.854,171.115 215.184,171.115 215.184,180.115 223.256,180.115 223.254,170.716 214.784,170.716 214.784,180.516 223.656,180.516 223.654,170.316 214.384,170.316 214.39,180.913 224.056,180.916 224.054,169.916 213.984,169.916 213.984,181.316 224.456,181.316 224.454,169.516 213.584,169.516 213.584,181.716 224.856,181.716 224.854,169.115 213.184,169.115 213.184,182.115 225.256,182.115 225.254,168.716 212.784,168.716 212.784,182.516 225.656,182.516 225.656,176.657 U8.2@229.794,176.657 ; C69.1@226.797,177.825 C53.1@227.762,177.825 C70.2@227.762,176.682
  Top Layer w0.254: pad.0@225.908,174.676 225.933,174.701 225.933,175.311 225.984,175.362 C70.1@227.762,175.362 ; C72.1@226.797,174.244 227.736,174.244 C71.1@227.762,174.269 C70.1@227.762,175.362 ; C70.1@227.762,175.412 C70.1@227.762,175.362 ; U8.3@229.756,175.362 C70.1@227.762,175.362
  Bottom Layer w0.2: pad.1@221.691,175.614 222.053,175.614 ; 222.055,175.615 222.053,179.316 215.983,179.316 215.983,171.916 222.455,171.916 222.453,179.716 215.583,179.716 215.583,171.516 222.855,171.516 222.853,180.115 215.183,180.115 215.183,171.115 223.255,171.115 223.253,180.516 214.783,180.516 214.783,170.716 223.655,170.716 223.653,180.916 214.383,180.916 214.389,170.318 224.055,170.316 224.053,181.316 213.983,181.316 213.983,169.916 224.455,169.916 224.453,181.716 213.583,181.716 213.583,169.516 224.855,169.516 224.853,182.115 213.183,182.115 213.183,169.115 225.255,169.115 225.253,182.516 212.783,182.516 212.783,168.716 225.655,168.716 225.655,174.676 pad.0@225.933,174.676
